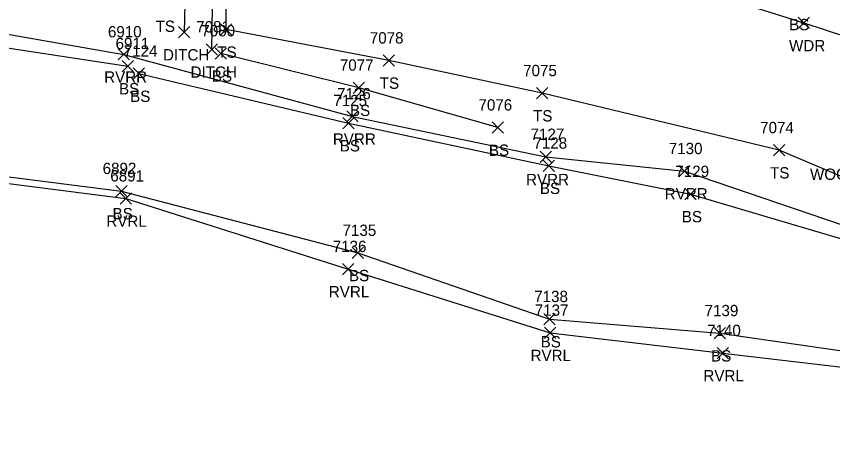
# Model space of a CAD drawing. Extents: x 1588028 to 1589597, y 137576 to 138176.
# Drawn here: x 1589306 to 1589450, y 137581.4 to 137659.5 of the extents above; entities that cross this region are included whole.
import ezdxf

# ---------------------------------------------------------------- set-up
doc = ezdxf.new("R2010")
doc.units = 0
for name, color, linetype in [('D_A', 7, 'Continuous'), ('D_I', 7, 'Continuous'), ('D_TIC', 7, 'Continuous'), ('DD', 7, 'Continuous'), ('L_A', 7, 'Continuous'), ('L_C', 7, 'Continuous'), ('L_I', 7, 'Continuous'), ('L_TIC', 7, 'Continuous'), ('LAWA', 7, 'Continuous'), ('LAWE', 7, 'Continuous'), ('LELB', 7, 'Continuous')]:
    doc.layers.add(name, color=color, linetype=linetype)

msp = doc.modelspace()

# ---------------------------------------------------------------- linework, layer by layer
at = {"layer": 'D_TIC'}
for points in [[(1589334.62, 137655.73), (1589336.62, 137657.73)], [(1589336.62, 137655.73), (1589334.62, 137657.73)], [(1589339.48, 137652.68), (1589341.48, 137654.68)], [(1589341.48, 137652.68), (1589339.48, 137654.68)]]:
    msp.add_lwpolyline(points, dxfattribs=at)
at = {"layer": 'DD'}
for points in [[(1589337.77, 137690.97), (1589335.95, 137671.63), (1589335.62, 137656.73)], [(1589340.48, 137653.68), (1589340.91, 137680.12)]]:
    msp.add_lwpolyline(points, dxfattribs=at)
at = {"layer": 'L_TIC'}
for points in [[(1589443.95, 137657.35), (1589445.95, 137659.35)], [(1589445.95, 137657.35), (1589443.95, 137659.35)], [(1589342.02, 137656.2), (1589344.02, 137658.2)], [(1589344.02, 137656.2), (1589342.02, 137658.2)], [(1589341.04, 137651.98), (1589343.04, 137653.98)], [(1589343.04, 137651.98), (1589341.04, 137653.98)], [(1589323.97, 137651.81), (1589325.97, 137653.81)], [(1589325.97, 137651.81), (1589323.97, 137653.81)], [(1589370.69, 137650.72), (1589372.69, 137652.72)], [(1589372.69, 137650.72), (1589370.69, 137652.72)], [(1589324.66, 137649.73), (1589326.66, 137651.73)], [(1589326.66, 137649.73), (1589324.66, 137651.73)], [(1589326.62, 137648.4), (1589328.62, 137650.4)], [(1589328.62, 137648.4), (1589326.62, 137650.4)], [(1589365.4, 137645.92), (1589367.4, 137647.92)], [(1589367.4, 137645.92), (1589365.4, 137647.92)], [(1589397.74, 137644.95), (1589399.74, 137646.95)], [(1589399.74, 137644.95), (1589397.74, 137646.95)], [(1589364.32, 137640.86), (1589366.32, 137642.86)], [(1589366.32, 137640.86), (1589364.32, 137642.86)], [(1589363.6, 137639.66), (1589365.6, 137641.66)], [(1589365.6, 137639.66), (1589363.6, 137641.66)], [(1589389.92, 137638.88), (1589391.92, 137640.88)], [(1589391.92, 137638.88), (1589389.92, 137640.88)], [(1589439.56, 137634.88), (1589441.56, 137636.88)], [(1589441.56, 137634.88), (1589439.56, 137636.88)], [(1589398.41, 137633.7), (1589400.41, 137635.7)], [(1589400.41, 137633.7), (1589398.41, 137635.7)], [(1589398.91, 137632.14), (1589400.91, 137634.14)], [(1589400.91, 137632.14), (1589398.91, 137634.14)], [(1589422.88, 137631.18), (1589424.88, 137633.18)], [(1589424.88, 137631.18), (1589422.88, 137633.18)], [(1589323.52, 137627.67), (1589325.52, 137629.67)], [(1589325.52, 137627.67), (1589323.52, 137629.67)], [(1589324.3, 137626.35), (1589326.3, 137628.35)], [(1589326.3, 137626.35), (1589324.3, 137628.35)], [(1589423.96, 137627.14), (1589425.96, 137629.14)], [(1589425.96, 137627.14), (1589423.96, 137629.14)], [(1589365.23, 137616.74), (1589367.23, 137618.74)], [(1589367.23, 137616.74), (1589365.23, 137618.74)], [(1589363.55, 137613.89), (1589365.55, 137615.89)], [(1589365.55, 137613.89), (1589363.55, 137615.89)], [(1589399.05, 137605.05), (1589401.05, 137607.05)], [(1589401.05, 137605.05), (1589399.05, 137607.05)], [(1589399.15, 137602.63), (1589401.15, 137604.63)], [(1589401.15, 137602.63), (1589399.15, 137604.63)], [(1589429.12, 137602.56), (1589431.12, 137604.56)], [(1589431.12, 137602.56), (1589429.12, 137604.56)], [(1589429.64, 137599.05), (1589431.64, 137601.05)], [(1589431.64, 137599.05), (1589429.64, 137601.05)]]:
    msp.add_lwpolyline(points, dxfattribs=at)
at = {"layer": 'LAWA'}
msp.add_lwpolyline([(1589349.24, 137689.61), (1589382.22, 137681.05), (1589414.78, 137667.9), (1589444.95, 137658.35), (1589471.13, 137649.8)], dxfattribs=at)
at = {"layer": 'LAWE'}
for points in [[(1588998.37, 137781.01), (1589022.99, 137780.11), (1589053.11, 137769.29), (1589085.17, 137761.52), (1589118.32, 137748.59), (1589139.23, 137719.4), (1589162.49, 137704.02), (1589194.14, 137678.84), (1589218.55, 137662.87), (1589237.06, 137655.88), (1589274.24, 137640.2), (1589299.98, 137630.61), (1589325.3, 137627.35), (1589364.55, 137614.89), (1589400.15, 137603.63), (1589430.64, 137600.05), (1589464.28, 137596.09), (1589486.71, 137581.4)], [(1589165.8, 137734.64), (1589187.94, 137715.26), (1589212.73, 137704.5), (1589228.51, 137693.02), (1589244.33, 137677.06), (1589269.62, 137665.25), (1589295.65, 137657.92), (1589324.97, 137652.81), (1589365.32, 137641.86), (1589399.41, 137634.7), (1589423.88, 137632.18), (1589457.23, 137620.82), (1589479.74, 137612.88)]]:
    msp.add_lwpolyline(points, dxfattribs=at)
at = {"layer": 'LELB'}
for points in [[(1588992.37, 137810.47), (1589023.33, 137801.66), (1589065.26, 137783.21), (1589085.4, 137777.87), (1589097.27, 137780.08), (1589112.23, 137773.55), (1589130.4, 137758.11), (1589147.06, 137743.95), (1589161.02, 137733.26), (1589186.97, 137714.57), (1589213.06, 137701.82), (1589227.47, 137691.94), (1589245.18, 137673.31), (1589268.48, 137660.8), (1589296.93, 137655.07), (1589325.66, 137650.73)], [(1588992.54, 137792.39), (1589023.3, 137782.03), (1589052.1, 137771.44), (1589084.42, 137763.28), (1589121.54, 137752.14), (1589143.04, 137720.61), (1589163.05, 137704.95), (1589194.58, 137680.14), (1589220, 137665.12), (1589237.76, 137657.31), (1589273.63, 137642.37), (1589300.04, 137631.76), (1589324.52, 137628.67), (1589366.23, 137617.74), (1589400.05, 137606.05), (1589430.12, 137603.56), (1589464.26, 137598.64), (1589483.45, 137589.04)], [(1589467.95, 137624.31), (1589440.56, 137635.88), (1589398.74, 137645.95), (1589371.69, 137651.72), (1589343.02, 137657.2), (1589343.09, 137676.77), (1589344.49, 137692.63)], [(1589390.92, 137639.88), (1589366.4, 137646.92), (1589342.04, 137652.98)], [(1589327.62, 137649.4), (1589364.6, 137640.66), (1589399.91, 137633.14), (1589424.96, 137628.14), (1589457.19, 137618.58), (1589481.39, 137610.02)]]:
    msp.add_lwpolyline(points, dxfattribs=at)

# ---------------------------------------------------------------- texts
at = {"layer": 'D_A'}
for p in [(1589331.86, 137651.73), (1589336.72, 137648.68)]:
    msp.add_text('DITCH', height=2, dxfattribs=at).set_placement(p)
at = {"layer": 'D_I'}
msp.add_text('7081', height=2, dxfattribs=at).set_placement((1589337.71, 137656.68))
at = {"layer": 'L_A'}
for s, p in [('TS', (1589330.56, 137656.77)), ('BS', (1589442.34, 137657.06)), ('WDR', (1589442.32, 137653.35)), ('TS', (1589341.43, 137652.2)), ('RVRR', (1589321.48, 137647.81)), ('BS', (1589340.48, 137647.98)), ('TS', (1589370.1, 137646.72)), ('BS', (1589324.1, 137645.73)), ('BS', (1589326.06, 137644.4)), ('BS', (1589364.84, 137641.92)), ('TS', (1589397.15, 137640.95)), ('RVRR', (1589361.83, 137636.86)), ('BS', (1589363.04, 137635.66)), ('BS', (1589389.36, 137634.88)), ('TS', (1589438.97, 137630.88)), ('RVRR', (1589395.92, 137629.7)), ('BS', (1589398.35, 137628.14)), ('RVRR', (1589420.39, 137627.18)), ('BS', (1589322.96, 137623.67)), ('BS', (1589423.4, 137623.14)), ('RVRL', (1589321.87, 137622.35)), ('BS', (1589364.67, 137612.74)), ('RVRL', (1589361.12, 137609.89)), ('BS', (1589398.49, 137601.05)), ('RVRL', (1589396.71, 137598.63)), ('BS', (1589428.56, 137598.56)), ('RVRL', (1589427.21, 137595.05))]:
    msp.add_text(s, height=2, dxfattribs=at).set_placement(p)
at = {"layer": 'L_C'}
msp.add_text('WOOD DECK PLATFORM W/ TEL BOXES', height=2, dxfattribs=at).set_placement((1589446.02, 137630.63))
at = {"layer": 'L_I'}
for s, p in [('6910', (1589322.14, 137655.81)), ('7080', (1589338.62, 137655.98)), ('6911', (1589323.49, 137653.73)), ('7078', (1589368.35, 137654.72)), ('7124', (1589324.93, 137652.4)), ('7077', (1589363.06, 137649.92)), ('7075', (1589395.4, 137648.95)), ('7126', (1589362.57, 137644.86)), ('7125', (1589361.91, 137643.66)), ('7076', (1589387.52, 137642.88)), ('7127', (1589396.71, 137637.7)), ('7074', (1589437.22, 137638.88)), ('7128', (1589397.21, 137636.14)), ('7130', (1589421.1, 137635.18)), ('6892', (1589321.21, 137631.67)), ('6891', (1589322.56, 137630.35)), ('7129', (1589422.26, 137631.14)), ('7135', (1589363.54, 137620.74)), ('7136', (1589361.81, 137617.89)), ('7138', (1589397.36, 137609.05)), ('7137', (1589397.45, 137606.63)), ('7139', (1589427.42, 137606.56)), ('7140', (1589427.86, 137603.05))]:
    msp.add_text(s, height=2, dxfattribs=at).set_placement(p)

doc.saveas('drawing.dxf')
